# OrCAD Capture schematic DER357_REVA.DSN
size C
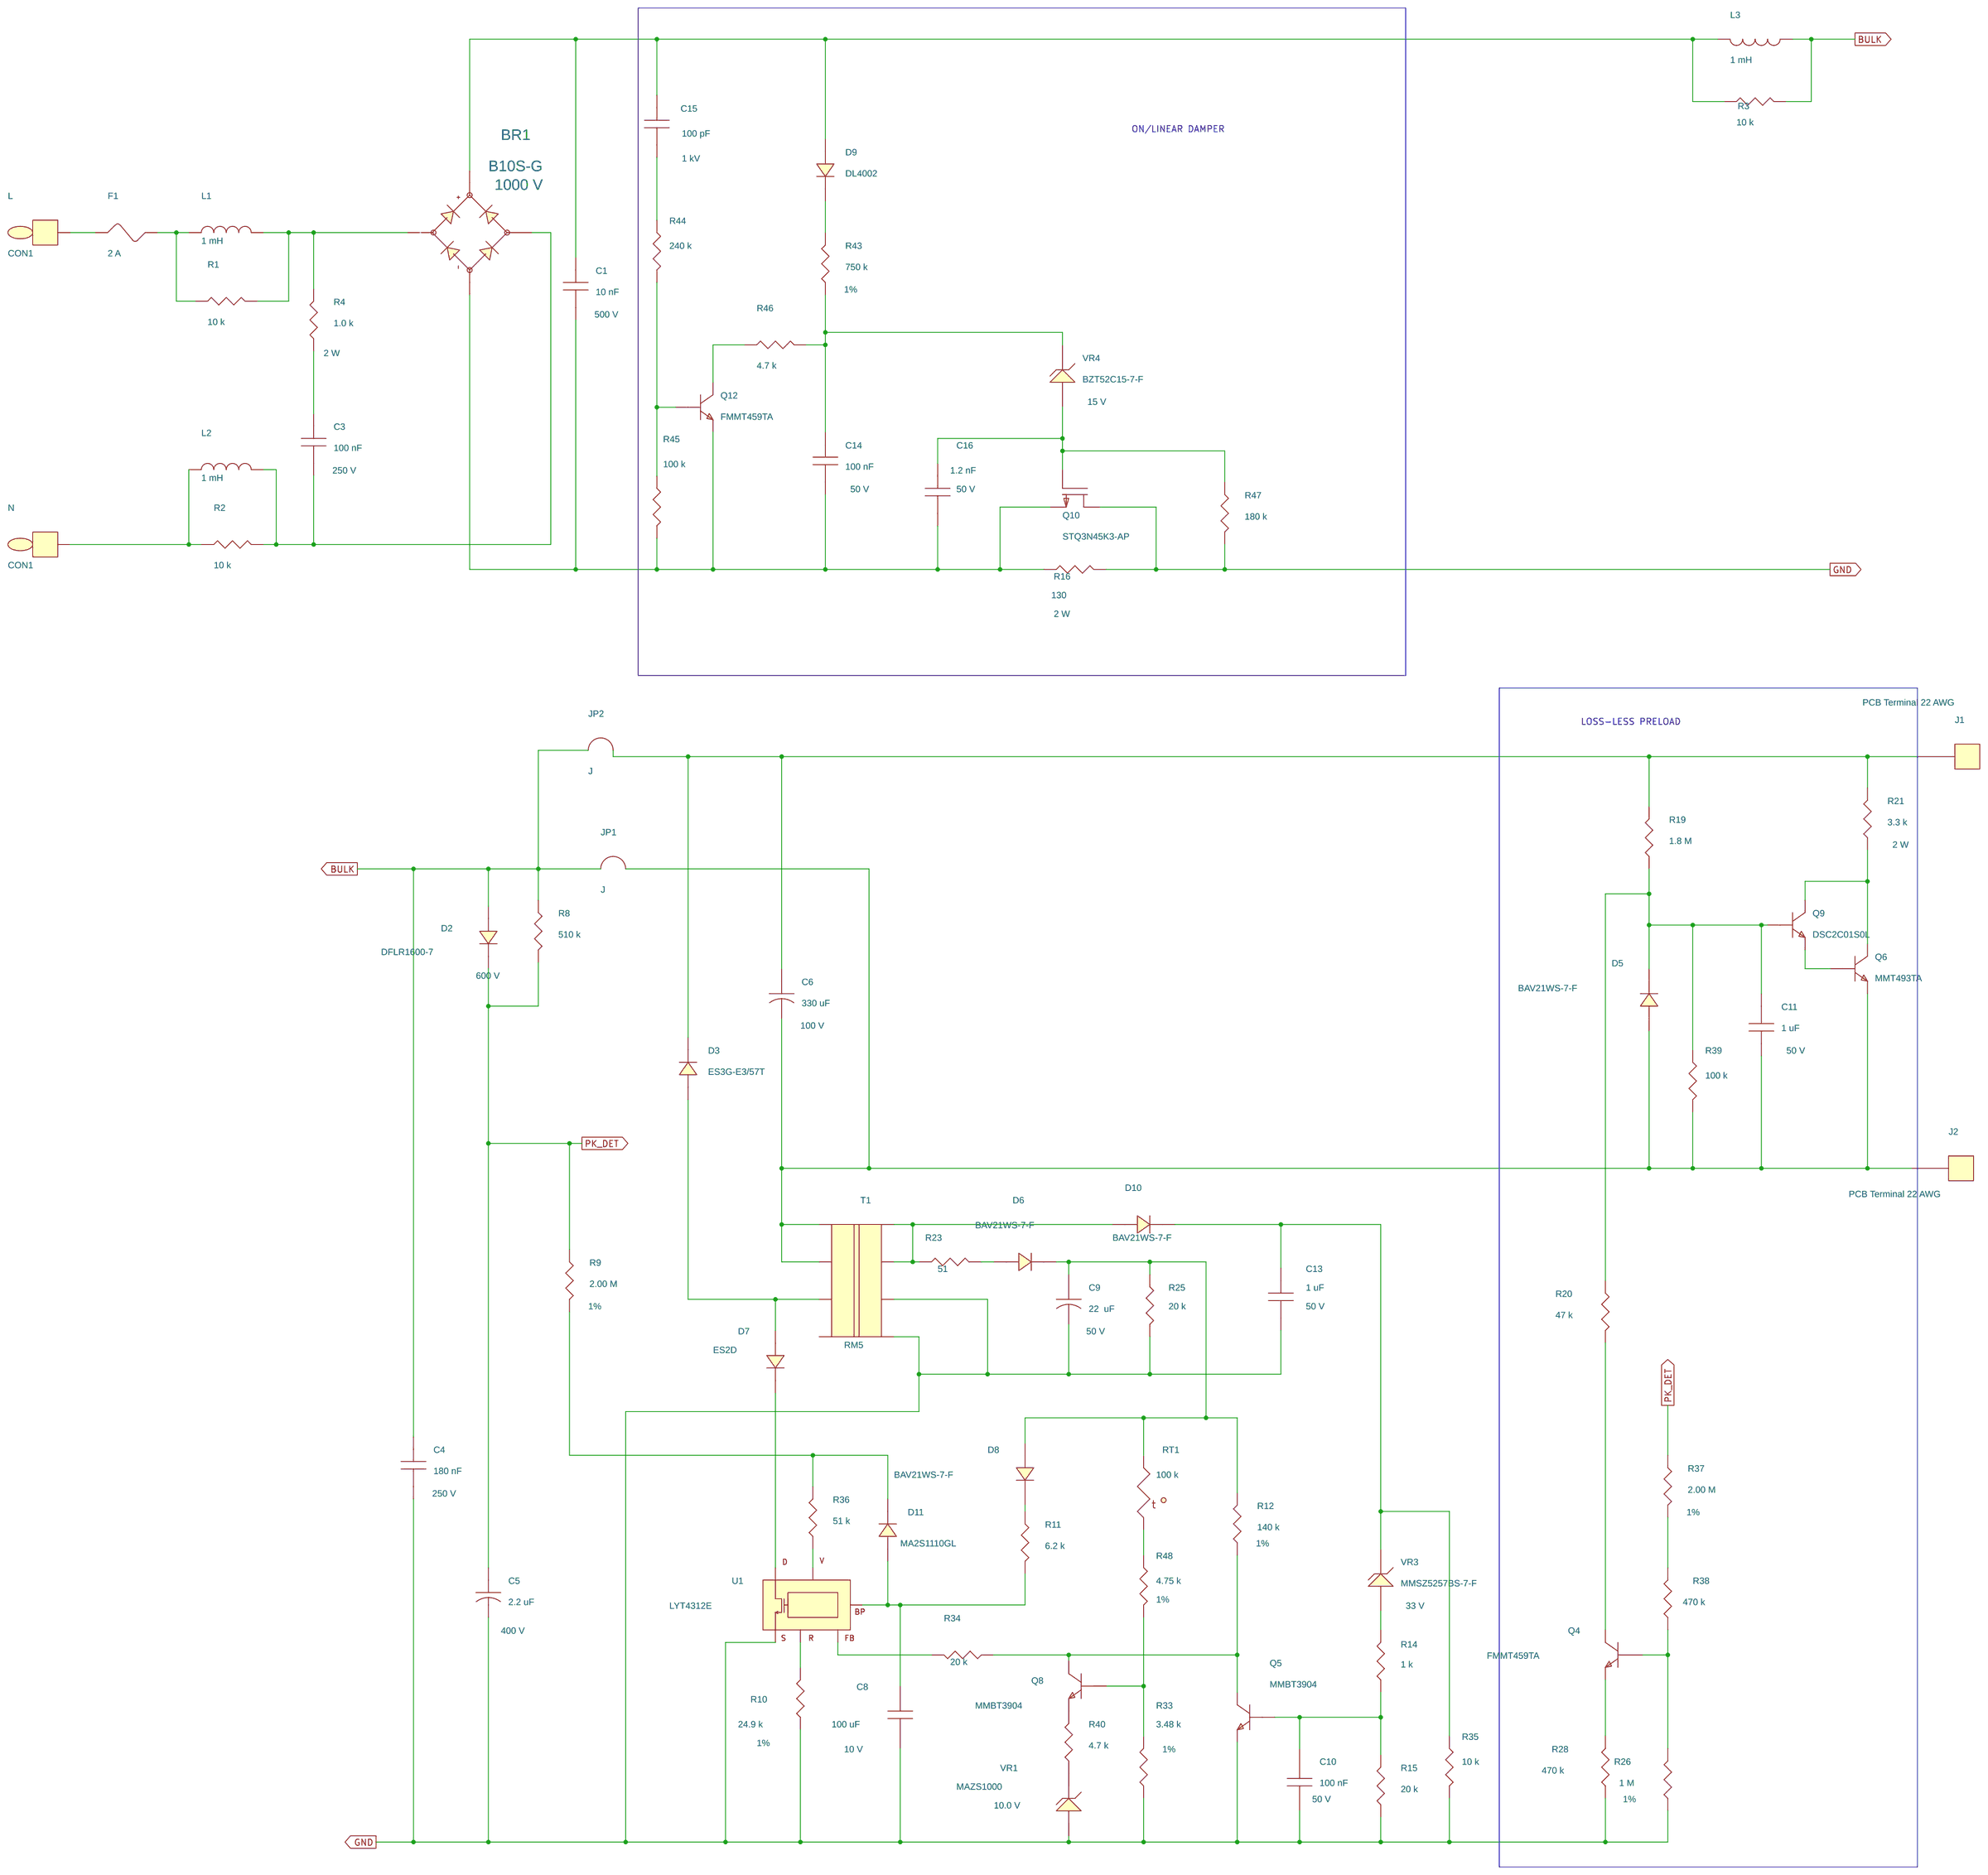
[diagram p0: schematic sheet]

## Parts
BR1  B10S-G  [pismsoic4]
C1  10 nF  [pinpcaprad440x160250030]
C3  100 nF  [pi_np_caprad320x235ls200d030]
C4  180 nF  [pinpcaprad440x200300040]
C5  2.2 uF  [pipolcapcyld250ls100030]
C6  330 uF  [pipolcapclyd500ls200040]
C8  100 uF  [pismc1206]
C9  22  uF  [pipolcapclyd200ls80030]
C10  100 nF  [pismc0603]
C11  1 uF  [pismc0805]
C13  1 uF  [pismc0805]
C14  100 nF  [pismc0805]
C15  100 pF  [pinpcaprad250x160250030]
C16  1.2 nF  [pismc0805]
D2  DFLR1600-7  [pismddflr120012]
D3  ES3G-E3/57T  [pismdo214ab12]
D5  BAV21WS-7-F  [pismsod323]
D6  BAV21WS-7-F  [pismsod323]
D7  ES2D  [pismdo214aa12]
D8  BAV21WS-7-F  [pismsod323]
D9  DL4002  [pismdmll4112]
D10  BAV21WS-7-F  [pismsod323]
D11  MA2S1110GL  [pismdsod52312]
F1  2 A  [pivaxiald100ls100030]
J1  PCB Terminal 22 AWG  [pi_hole_22awg]
J2  PCB Terminal 22 AWG  [pi_hole_22awg]
JP1  J  [pi_jumper300]
JP2  J  [pi_jumper300]
L  CON1  [pitpkeystone100x100]
L1  1 mH  [pichoke030dials200035]
L2  1 mH  [pichoke030dials200035]
L3  1 mH  [pichoke030dials200035]
N  CON1  [pitpkeystone100x100]
Q4  FMMT459TA  [pismsot23132]
Q5  MMBT3904  [pismsot23132]
Q6  MMT493TA  [pismsot23132]
Q8  MMBT3904  [pismsot23132]
Q9  DSC2C01S0L  [pismsot23132]
Q10  STQ3N45K3-AP  [PIT092100]
Q12  FMMT459TA  [pismsot23132]
R1  10 k  [pismr0805]
R2  10 k  [pismr0805]
R3  10 k  [pismr0805]
R4  1.0 k  [pi12wvresd180ls150d040]
R8  510 k  [pismr1206]
R9  2.00 M  [pi14wresd100ls500d030]
R10  24.9 k  [pi14wresd100ls400d030]
R11  6.2 k  [pismr0603]
R12  140 k  [pismr0603]
R14  1 k  [pismr0603]
R15  20 k  [pismr0603]
R16  130  [pi2wresd200ls725d040]
R19  1.8 M  [pismr0805]
R20  47 k  [pismr1206]
R21  3.3 k  [pi2wresd200ls725d040]
R23  51  [pismr0805]
R25  20 k  [pismr0805]
R26  1 M  [pismr0805]
R28  470 k  [pismr0805]
R33  3.48 k  [pismr0603]
R34  20 k  [pismr0603]
R35  10 k  [pismr0805]
R36  51 k  [pismr0603]
R37  2.00 M  [pismr1206]
R38  470 k  [pismr0805]
R39  100 k  [pismr0805]
R40  4.7 k  [pismr0603]
R43  750 k  [pismr1206]
R44  240 k  [pismr1206]
R45  100 k  [pismr0603]
R46  4.7 k  [pismr0805]
R47  180 k  [pismr0805]
R48  4.75 k  [pismr0603]
RT1  100 k  [pi_rad_118x118_ls100d025]
T1  RM5  [pi_bobbin_rm5_6p_clp]
U1  LYT4312E  [piicesip76th]
VR1  MAZS1000  [pismdsod52312]
VR3  MMSZ5257BS-7-F  [pismsod323]
VR4  BZT52C15-7-F  [pi_sm_sod-123_12]

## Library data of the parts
BR1 = DIODE_BRIDGE_~~+-: Disp_Voltage: 1000 V; Part Number: 15-00818-00; ROOM: 1
C1 = CAP_NP: Disp_Voltage: 500 V; Part Number: 20-00652-00; ROOM: 1; Voltage: 500 V
C3 = CAP_NP: Disp_Voltage: 250 V; Part Number: 20-00930-00; ROOM: 1; Voltage: 250 V
C4 = CAP_NP: Disp_Voltage: 250 V; Part Number: 20-08588-00; Voltage: 250 V
C5 = CAP_POL: ALT_SYMBOLS: pipolcapcyld250ls100030h; Disp_Voltage: 400 V; Part Number: 20-01008-00; Voltage: 400 V
C6 = CAP_POL: ALT_SYMBOLS: pipolcapclyd500ls2000401000lh; Disp_Voltage: 100 V; FPLIST: pipolcapclyd500ls200040,pipolcapclyd500ls2000401000lh; Part Number: 20-01042-00; Voltage: 100 V
C8 = CAP_NP: Disp_Voltage: 10 V; Part Number: 20-01019-00; Voltage: 10 V
C9 = CAP_POL: Disp_Voltage: 50 V; Part Number: 20-00950-00; Voltage: 50 V
C10 = CAP_NP: Disp_Voltage: 50 V; Part Number: 20-00936-00; Voltage: 50 V
C11 = CAP_NP: Disp_Voltage: 50 V; Part Number: 20-00853-00; Voltage: 50 V
C13 = CAP_NP_1: Disp_Voltage: 50 V; Part Number: 20-00853-00; Tol: 10; Voltage: 50 V
C14 = CAP_NP: Disp_Voltage: 50 V; Part Number: 20-00904-00; Voltage: 50 V
C15 = CAP_NP: Disp_Voltage: 1 kV; Part Number: 20-00654-00; Voltage: 1 kV
C16 = CAP_NP: Disp_Voltage: 50 V; Part Number: 20-00210-00; Voltage: 50 V
D2 = DIODE: Disp_Voltage: 600 V; Part Number: 15-00826-00
D3 = DIODE: Part Number: 15-00979-00
D5 D6 D8 D10 = DIODE: Part Number: 15-00385-00
D7 = DIODE: Part Number: 15-00171-00
D9 = DIODE: GROUP: 1; Part Number: 15-00701-00; ROOM: 1
D11 = DIODE: Part Number: 15-00686-00
F1 = FUSE: FPLIST: pivaxiald100ls100030,piaxiald100ls500030,pi12wvresd180ls200d040; Part Number: 40-00025-00; ROOM: 1
J1 J2 = TERM_1Pin: Part Number: 35-00008-00
JP1 JP2 = JUMPER_1: Part Number: 65-00042-00
L N = TESTPOINT: Part Number: 35-00079-00; ROOM: 1
L1-L3 = INDUCTOR: Part Number: 30-00169-00; ROOM: 1
Q4 Q12 = NPN_BEC: Part Number: 55-00074-00
Q5 Q8 = NPN_BEC: Part Number: 55-00048-00
Q6 = NPN_BEC: Part Number: 55-00104-00
Q9 = NPN_BEC: Part Number: 55-00103-00
Q10 = FET_N_GDS: FPLIST: PITO92R100,PIT092100; Part Number: 50-00118-00
R1-R3 = R: Part Number: 05-01543-00; ROOM: 1
R4 = R: ALT_SYMBOLS: pi12wvresd180ls200d040,pi12wvresd180ls250d040,pi12wresd180ls675d040; Disp_Power: 2 W; FPLIST: pi12wvresd180ls150d040,pi12wvresd180ls200d040,pi12wvresd180ls250d040,pi12wresd180ls675d040; Part Number: 05-05397-00; ROOM: 1
R8 = R: Part Number: 05-01417-00
R9 = R: ALT_SYMBOLS: pi14wvresd100ls200d030,pi14wresd100ls400d030,pi14wresd100ls500d030; Disp_Tol: 1%; FPLIST: pi14wvresd100ls100d030,pi14wvresd100ls200d030,pi14wresd100ls400d030,pi14wresd100ls500d030; Part Number: 05-05389-00
R10 = R: ALT_SYMBOLS: pi14wvresd100ls200d030,pi14wresd100ls400d030,pi14wresd100ls500d030; Disp_Tol: 1%; FPLIST: pi14wvresd100ls100d030,pi14wvresd100ls200d030,pi14wresd100ls400d030,pi14wresd100ls500d030; Part Number: 05-02110-00
R11 = R: Part Number: 05-01707-00
R12 = R: Disp_Tol: 1%; Part Number: 05-01188-00
R14 = R: Part Number: 05-01688-00
R15 R34 = R: Part Number: 05-01719-00
R16 = R: ALT_SYMBOLS: pi2wresd200ls900d040,pi2wvresd200ls300d040,pi2wvresd200ls400d040; Disp_Power: 2 W; FPLIST: pi2wresd200ls725d040,pi2wresd200ls900d040,pi2wvresd200ls300d040,pi2wvresd200ls400d040; PCB Editor PCBFP: pi12wvresd180ls150d040,pi12wvresd180ls200d040,pi12wvresd180ls250d040,pi12wresd180ls675d040; Part Number: 05-02983-00; Tol: 5%
R19 = R: Part Number: 05-01597-00
R20 = R: Part Number: 05-01392-00
R21 = R: ALT_SYMBOLS: pi2wresd200ls900d040,pi2wvresd200ls300d040,pi2wvresd200ls400d040; Disp_Power: 2 W; FPLIST: pi2wresd200ls725d040,pi2wresd200ls900d040,pi2wvresd200ls300d040,pi2wvresd200ls400d040; Part Number: 05-03016-00
R23 = R: Part Number: 05-01488-00
R25 = R: Part Number: 05-01550-00
R26 = R: Disp_Tol: 1%; Part Number: 05-00876-00
R28 R38 = R: Part Number: 05-01583-00
R33 = R: Disp_Tol: 1%; Part Number: 05-01130-00
R35 = R: PCB Editor PCBFP: pi14wvresd100ls100d030,pi14wvresd100ls200d030,pi14wresd100ls400d030,pi14wresd100ls500d030; Part Number: 05-01543-00; Tol: 5%
R36 = R: Part Number: 05-01729-00
R37 = R: Disp_Tol: 1%; Part Number: 05-03156-00
R39 = R: Part Number: 05-01567-00
R40 = R: Part Number: 05-01704-00
R43 = R: Disp_Tol: 1%; Part Number: 05-00469-00
R44 = R: Part Number: 05-01409-00
R45 = R: Part Number: 05-01736-00
R46 = R: Part Number: 05-01535-00
R47 = R: Part Number: 05-01573-00
R48 = R: Disp_Tol: 1%; Part Number: 05-01143-00
RT1 = THERMISTOR: Part Number: 91-00005-00
T1 = BRM6_6P_CLP: Part Number: 25-00989-00
U1 = LNK40X_eSIP: Part Number: 10-00639-00
VR1 = DIODE_ZENER: Disp_Voltage: 10.0 V; Part Number: 15-00420-00
VR3 = DIODE_ZENER: Disp_Voltage: 33 V; Part Number: 15-00992-00
VR4 = DIODE_ZENER: Disp_Voltage: 15 V; Part Number: 15-00923-00

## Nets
GND: C4.2 C5.2 C8.2 C9.2 C10.1 C13.2 Q5.2(EMITTER) Q10.2(D) R10.1 R15.1 R16.2 R25.2 R26.2 R28.2 R33.1 R35.2 R47.2 T1.3 T1.CLP2 U1.5(S) VR1.2
BULK: C4.1 D2.2 JP1.1 JP2.1 L3.1 R3.2 R8.1
PK_DET: C5.1 D2.1 R8.2 R9.1 R37.1
N2191708: F1.1 L1.1 R1.1
N2229506: BR1.4 C1.2 C14.2 C16.2 Q10.3(S) Q12.2(EMITTER) R16.1 R45.2
N2232323: L2.1 N.1 R2.1
N2302506: F1.2 L.1
N2488145: BR1.1 C3.2 L2.2 R2.2
N2488295: BR1.2 L1.2 R1.2 R4.1
N2491459: C8.1 D11.2 R11.2 U1.4(BP)
N2492720: D7.1 U1.7(D)
N2492766: R10.2 U1.1(R)
N2493445: C6.2 C11.1 D5.2 J2.1 JP1.2 Q6.2(EMITTER) R39.2 T1.1 T1.2
N2532048: R34.2 U1.3(FB)
N2538393: BR1.3 C1.1 C15.1 D9.2 L3.2 R3.1
N2539922: C9.1 D6.1 D8.2 R12.2 R25.1 RT1.1
N2541951: D11.1 R9.2 R36.2
N3203198: R14.2 VR3.2
N3203318: C10.2 Q5.1(BASE) R14.1 R15.2
N3653162: C3.1 R4.2
N3672068: C6.1 D3.1 J1.1 JP2.2 R19.2 R21.1
N3707878: D3.2 D7.2 T1.6
N3708267: D6.2 R23.2
N3717582: Q4.1(BASE) R26.1 R38.2
N3718510: C11.2 D5.1 Q9.1(BASE) R19.1 R20.1 R39.1
N3718685: D8.1 R11.1
N3718886: Q5.3(COLLECTOR) Q8.3(COLLECTOR) R12.1 R34.1
N3734797: Q4.2(EMITTER) R28.1
N3737040: Q8.1(BASE) R33.2 R48.2
N3739420: C13.1 D10.1 R35.1 VR3.1
N3740281: R36.1 U1.2(V)
N3740360: D10.2 R23.1 T1.4 T1.5
N3742281: Q4.3(COLLECTOR) R20.2
N3742707: R37.2 R38.1
N3743778: Q6.1(BASE) Q9.2(EMITTER)
N3743785: Q6.3(COLLECTOR) Q9.3(COLLECTOR) R21.2
N3766853: C15.2 R44.1
N3766857: Q12.1(BASE) R44.2 R45.1
N3768407: Q12.3(COLLECTOR) R46.1
N3768414: C14.1 R43.1 R46.2 VR4.1
N3769856: D9.1 R43.2
N3777751: C16.1 Q10.1(G) R47.1 VR4.2
N3792762: R48.1 RT1.2
N3798621: Q8.2(EMITTER) R40.2
N3798622: R40.1 VR1.1

Not connected (* = marked no-connect by the designer): T1 CLP1

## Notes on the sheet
- ON/LINEAR DAMPER
- LOSS-LESS PRELOAD
